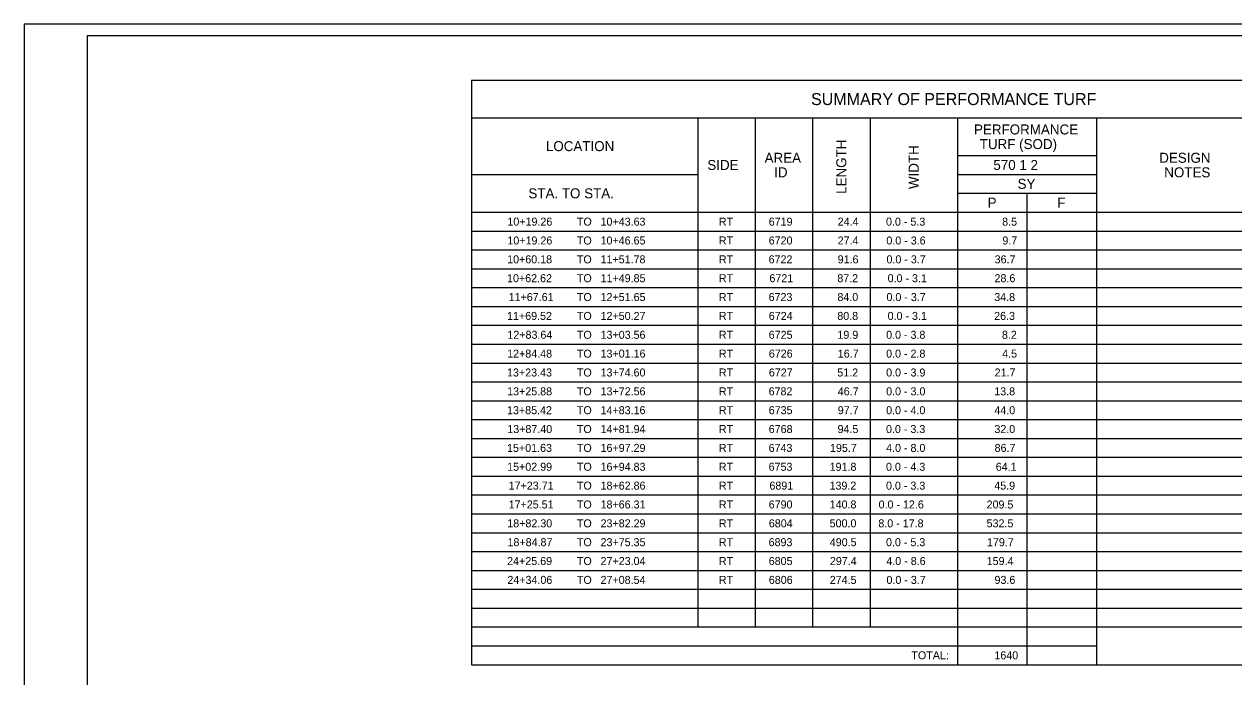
# Model space of a CAD drawing. Extents: x -831.4 to -734.9, y -2212.7 to -2202.1.
# Drawn here: x -751.39 to -740.81, y -2207.85 to -2202.14 of the extents above; entities that cross this region are included whole.
import ezdxf

# ---------------------------------------------------------------- set-up
doc = ezdxf.new("R2010")
doc.units = 0
for name, color, linetype in [('PlotBorder_dp', 7, 'Continuous'), ('SheetBorder_dp', 7, 'Continuous'), ('SumBoxBorder_dp', 7, 'Continuous'), ('SumBoxLines_dp', 7, 'Continuous'), ('SumBoxLinesMin_dp', 7, 'Continuous'), ('TextLabel', 7, 'Continuous')]:
    doc.layers.add(name, color=color, linetype=linetype)

msp = doc.modelspace()

# ---------------------------------------------------------------- linework, layer by layer
at = {"layer": 'PlotBorder_dp'}
msp.add_lwpolyline([(-751.391, -2212.74), (-734.891, -2212.74), (-734.891, -2202.14), (-751.391, -2202.14)], close=True, dxfattribs=at)
at = {"layer": 'SheetBorder_dp'}
for q in [(-750.841, -2212.64), (-735.441, -2202.24)]:
    msp.add_line((-750.841, -2202.24), q, dxfattribs=at)
at = {"layer": 'SumBoxBorder_dp'}
for p, q in [((-747.479, -2202.63), (-738.802, -2202.63)), ((-747.479, -2202.63), (-747.479, -2207.745)), ((-747.479, -2207.745), (-738.802, -2207.745))]:
    msp.add_line(p, q, dxfattribs=at)
at = {"layer": 'SumBoxLines_dp'}
for p, q in [((-747.479, -2202.96), (-738.802, -2202.96)), ((-747.479, -2202.96), (-738.802, -2202.96)), ((-745.499, -2202.96), (-745.499, -2207.415)), ((-745.499, -2202.96), (-745.499, -2207.415)), ((-744.997, -2202.96), (-744.997, -2207.415)), ((-744.997, -2202.96), (-744.997, -2207.415)), ((-744.494, -2202.96), (-744.494, -2207.415)), ((-744.494, -2202.96), (-744.494, -2207.415)), ((-743.992, -2202.96), (-743.992, -2207.415)), ((-743.992, -2202.96), (-743.992, -2207.415)), ((-743.227, -2202.96), (-743.227, -2207.745)), ((-743.227, -2202.96), (-743.227, -2207.745)), ((-742.012, -2202.96), (-742.012, -2207.745)), ((-742.012, -2202.96), (-742.012, -2207.745)), ((-743.227, -2203.29), (-742.012, -2203.29)), ((-743.227, -2203.29), (-742.012, -2203.29)), ((-747.479, -2203.455), (-745.499, -2203.455)), ((-747.479, -2203.455), (-745.499, -2203.455)), ((-743.227, -2203.455), (-742.012, -2203.455)), ((-743.227, -2203.455), (-742.012, -2203.455)), ((-743.227, -2203.62), (-742.012, -2203.62)), ((-743.227, -2203.62), (-742.012, -2203.62)), ((-747.479, -2203.785), (-738.802, -2203.785)), ((-747.479, -2203.785), (-738.802, -2203.785)), ((-747.479, -2207.415), (-743.227, -2207.415)), ((-742.012, -2207.415), (-738.802, -2207.415))]:
    msp.add_line(p, q, dxfattribs=at)
at = {"layer": 'SumBoxLinesMin_dp'}
for p, q in [((-742.619, -2203.62), (-742.619, -2207.745)), ((-742.619, -2203.62), (-742.619, -2207.745)), ((-747.479, -2203.95), (-738.802, -2203.95)), ((-747.479, -2203.95), (-738.802, -2203.95)), ((-747.479, -2204.115), (-738.802, -2204.115)), ((-747.479, -2204.115), (-738.802, -2204.115)), ((-747.479, -2204.28), (-738.802, -2204.28)), ((-747.479, -2204.28), (-738.802, -2204.28)), ((-747.479, -2204.445), (-738.802, -2204.445)), ((-747.479, -2204.445), (-738.802, -2204.445)), ((-747.479, -2204.61), (-738.802, -2204.61)), ((-747.479, -2204.61), (-738.802, -2204.61)), ((-747.479, -2204.775), (-738.802, -2204.775)), ((-747.479, -2204.775), (-738.802, -2204.775)), ((-747.479, -2204.94), (-738.802, -2204.94)), ((-747.479, -2204.94), (-738.802, -2204.94)), ((-747.479, -2205.105), (-738.802, -2205.105)), ((-747.479, -2205.105), (-738.802, -2205.105)), ((-747.479, -2205.27), (-738.802, -2205.27)), ((-747.479, -2205.27), (-738.802, -2205.27)), ((-747.479, -2205.435), (-738.802, -2205.435)), ((-747.479, -2205.435), (-738.802, -2205.435)), ((-747.479, -2205.6), (-738.802, -2205.6)), ((-747.479, -2205.6), (-738.802, -2205.6)), ((-747.479, -2205.765), (-738.802, -2205.765)), ((-747.479, -2205.765), (-738.802, -2205.765)), ((-747.479, -2205.93), (-738.802, -2205.93)), ((-747.479, -2205.93), (-738.802, -2205.93)), ((-747.479, -2206.095), (-738.802, -2206.095)), ((-747.479, -2206.095), (-738.802, -2206.095)), ((-747.479, -2206.26), (-738.802, -2206.26)), ((-747.479, -2206.26), (-738.802, -2206.26)), ((-747.479, -2206.425), (-738.802, -2206.425)), ((-747.479, -2206.425), (-738.802, -2206.425)), ((-747.479, -2206.59), (-738.802, -2206.59)), ((-747.479, -2206.59), (-738.802, -2206.59)), ((-747.479, -2206.755), (-738.802, -2206.755)), ((-747.479, -2206.755), (-738.802, -2206.755)), ((-747.479, -2206.92), (-738.802, -2206.92)), ((-747.479, -2206.92), (-738.802, -2206.92)), ((-747.479, -2207.085), (-738.802, -2207.085)), ((-747.479, -2207.085), (-738.802, -2207.085)), ((-747.479, -2207.25), (-738.802, -2207.25)), ((-747.479, -2207.25), (-738.802, -2207.25)), ((-743.227, -2207.415), (-742.012, -2207.415)), ((-743.227, -2207.415), (-742.012, -2207.415)), ((-747.479, -2207.58), (-742.012, -2207.58)), ((-747.479, -2207.58), (-742.012, -2207.58))]:
    msp.add_line(p, q, dxfattribs=at)

# ---------------------------------------------------------------- texts
at = {"layer": 'TextLabel'}
for s, height, p in [('SUMMARY OF PERFORMANCE TURF', 0.105, (-744.508, -2202.848)), ('PERFORMANCE', 0.0875, (-743.082, -2203.105)), ('TURF (SOD)', 0.0875, (-743.032, -2203.233)), ('LOCATION', 0.0875, (-746.827, -2203.251)), ('AREA', 0.0875, (-744.914, -2203.353)), ('DESIGN', 0.0875, (-741.462, -2203.353)), ('SIDE', 0.0875, (-745.415, -2203.416)), ('570 1 2', 0.0875, (-742.913, -2203.416)), ('ID', 0.0875, (-744.83, -2203.48)), ('NOTES', 0.0875, (-741.418, -2203.48)), ('STA. TO STA.', 0.0875, (-746.98, -2203.664)), ('SY', 0.0875, (-742.701, -2203.581)), ('P', 0.0875, (-742.963, -2203.746)), ('F', 0.0875, (-742.354, -2203.746)), ('10+19.26', 0.07, (-747.164, -2203.903)), ('TO', 0.07, (-746.556, -2203.903)), ('10+43.63', 0.07, (-746.349, -2203.903)), ('RT', 0.07, (-745.314, -2203.903)), ('6719', 0.07, (-744.878, -2203.903)), ('24.4', 0.07, (-744.275, -2203.903)), ('0.0 - 5.3', 0.07, (-743.852, -2203.903)), ('8.5', 0.07, (-742.836, -2203.903)), ('10+19.26', 0.07, (-747.164, -2204.068)), ('TO', 0.07, (-746.556, -2204.068)), ('10+46.65', 0.07, (-746.349, -2204.068)), ('RT', 0.07, (-745.314, -2204.068)), ('6720', 0.07, (-744.878, -2204.068)), ('27.4', 0.07, (-744.275, -2204.068)), ('0.0 - 3.6', 0.07, (-743.849, -2204.068)), ('9.7', 0.07, (-742.834, -2204.068)), ('10+60.18', 0.07, (-747.166, -2204.233)), ('TO', 0.07, (-746.556, -2204.233)), ('11+51.78', 0.07, (-746.349, -2204.233)), ('RT', 0.07, (-745.314, -2204.233)), ('6722', 0.07, (-744.879, -2204.233)), ('91.6', 0.07, (-744.275, -2204.233)), ('0.0 - 3.7', 0.07, (-743.848, -2204.233)), ('36.7', 0.07, (-742.902, -2204.233)), ('10+62.62', 0.07, (-747.167, -2204.398)), ('TO', 0.07, (-746.556, -2204.398)), ('11+49.85', 0.07, (-746.349, -2204.398)), ('RT', 0.07, (-745.314, -2204.398)), ('6721', 0.07, (-744.872, -2204.398)), ('87.2', 0.07, (-744.278, -2204.398)), ('0.0 - 3.1', 0.07, (-743.838, -2204.398)), ('28.6', 0.07, (-742.903, -2204.398)), ('11+67.61', 0.07, (-747.153, -2204.563)), ('TO', 0.07, (-746.556, -2204.563)), ('12+51.65', 0.07, (-746.349, -2204.563)), ('RT', 0.07, (-745.314, -2204.563)), ('6723', 0.07, (-744.879, -2204.563)), ('84.0', 0.07, (-744.277, -2204.563)), ('0.0 - 3.7', 0.07, (-743.848, -2204.563)), ('34.8', 0.07, (-742.905, -2204.563)), ('11+69.52', 0.07, (-747.167, -2204.728)), ('TO', 0.07, (-746.556, -2204.728)), ('12+50.27', 0.07, (-746.349, -2204.728)), ('RT', 0.07, (-745.314, -2204.728)), ('6724', 0.07, (-744.877, -2204.728)), ('80.8', 0.07, (-744.278, -2204.728)), ('0.0 - 3.1', 0.07, (-743.838, -2204.728)), ('26.3', 0.07, (-742.906, -2204.728)), ('12+83.64', 0.07, (-747.164, -2204.893)), ('TO', 0.07, (-746.556, -2204.893)), ('13+03.56', 0.07, (-746.349, -2204.893)), ('RT', 0.07, (-745.314, -2204.893)), ('6725', 0.07, (-744.878, -2204.893)), ('19.9', 0.07, (-744.277, -2204.893)), ('0.0 - 3.8', 0.07, (-743.851, -2204.893)), ('8.2', 0.07, (-742.838, -2204.893)), ('12+84.48', 0.07, (-747.166, -2205.058)), ('TO', 0.07, (-746.556, -2205.058)), ('13+01.16', 0.07, (-746.349, -2205.058)), ('RT', 0.07, (-745.314, -2205.058)), ('6726', 0.07, (-744.877, -2205.058)), ('16.7', 0.07, (-744.274, -2205.058)), ('0.0 - 2.8', 0.07, (-743.851, -2205.058)), ('4.5', 0.07, (-742.836, -2205.058)), ('13+23.43', 0.07, (-747.167, -2205.223)), ('TO', 0.07, (-746.556, -2205.223)), ('13+74.60', 0.07, (-746.349, -2205.223)), ('RT', 0.07, (-745.314, -2205.223)), ('6727', 0.07, (-744.877, -2205.223)), ('51.2', 0.07, (-744.278, -2205.223)), ('0.0 - 3.9', 0.07, (-743.851, -2205.223)), ('21.7', 0.07, (-742.902, -2205.223)), ('13+25.88', 0.07, (-747.166, -2205.388)), ('TO', 0.07, (-746.556, -2205.388)), ('13+72.56', 0.07, (-746.349, -2205.388)), ('RT', 0.07, (-745.314, -2205.388)), ('6782', 0.07, (-744.879, -2205.388)), ('46.7', 0.07, (-744.274, -2205.388)), ('0.0 - 3.0', 0.07, (-743.851, -2205.388)), ('13.8', 0.07, (-742.905, -2205.388)), ('13+85.42', 0.07, (-747.167, -2205.553)), ('TO', 0.07, (-746.556, -2205.553)), ('14+83.16', 0.07, (-746.349, -2205.553)), ('RT', 0.07, (-745.314, -2205.553)), ('6735', 0.07, (-744.878, -2205.553)), ('97.7', 0.07, (-744.274, -2205.553)), ('0.0 - 4.0', 0.07, (-743.851, -2205.553)), ('44.0', 0.07, (-742.904, -2205.553)), ('13+87.40', 0.07, (-747.165, -2205.718)), ('TO', 0.07, (-746.556, -2205.718)), ('14+81.94', 0.07, (-746.349, -2205.718)), ('RT', 0.07, (-745.314, -2205.718)), ('6768', 0.07, (-744.878, -2205.718)), ('94.5', 0.07, (-744.276, -2205.718)), ('0.0 - 3.3', 0.07, (-743.852, -2205.718)), ('32.0', 0.07, (-742.904, -2205.718)), ('15+01.63', 0.07, (-747.167, -2205.883)), ('TO', 0.07, (-746.556, -2205.883)), ('16+97.29', 0.07, (-746.349, -2205.883)), ('RT', 0.07, (-745.314, -2205.883)), ('6743', 0.07, (-744.879, -2205.883)), ('195.7', 0.07, (-744.342, -2205.883)), ('4.0 - 8.0', 0.07, (-743.851, -2205.883)), ('86.7', 0.07, (-742.902, -2205.883)), ('15+02.99', 0.07, (-747.166, -2206.048)), ('TO', 0.07, (-746.556, -2206.048)), ('16+94.83', 0.07, (-746.349, -2206.048)), ('RT', 0.07, (-745.314, -2206.048)), ('6753', 0.07, (-744.879, -2206.048)), ('191.8', 0.07, (-744.345, -2206.048)), ('0.0 - 4.3', 0.07, (-743.852, -2206.048)), ('64.1', 0.07, (-742.892, -2206.048)), ('17+23.71', 0.07, (-747.153, -2206.213)), ('TO', 0.07, (-746.556, -2206.213)), ('18+62.86', 0.07, (-746.349, -2206.213)), ('RT', 0.07, (-745.314, -2206.213)), ('6891', 0.07, (-744.872, -2206.213)), ('139.2', 0.07, (-744.346, -2206.213)), ('0.0 - 3.3', 0.07, (-743.852, -2206.213)), ('45.9', 0.07, (-742.905, -2206.213)), ('17+25.51', 0.07, (-747.153, -2206.378)), ('TO', 0.07, (-746.556, -2206.378)), ('18+66.31', 0.07, (-746.349, -2206.378)), ('RT', 0.07, (-745.314, -2206.378)), ('6790', 0.07, (-744.878, -2206.378)), ('140.8', 0.07, (-744.345, -2206.378)), ('0.0 - 12.6', 0.07, (-743.917, -2206.378)), ('209.5', 0.07, (-742.972, -2206.378)), ('18+82.30', 0.07, (-747.165, -2206.543)), ('TO', 0.07, (-746.556, -2206.543)), ('23+82.29', 0.07, (-746.349, -2206.543)), ('RT', 0.07, (-745.314, -2206.543)), ('6804', 0.07, (-744.877, -2206.543)), ('500.0', 0.07, (-744.345, -2206.543)), ('8.0 - 17.8', 0.07, (-743.919, -2206.543)), ('532.5', 0.07, (-742.972, -2206.543)), ('18+84.87', 0.07, (-747.163, -2206.708)), ('TO', 0.07, (-746.556, -2206.708)), ('23+75.35', 0.07, (-746.349, -2206.708)), ('RT', 0.07, (-745.314, -2206.708)), ('6893', 0.07, (-744.879, -2206.708)), ('490.5', 0.07, (-744.344, -2206.708)), ('0.0 - 5.3', 0.07, (-743.852, -2206.708)), ('179.7', 0.07, (-742.969, -2206.708)), ('24+25.69', 0.07, (-747.166, -2206.873)), ('TO', 0.07, (-746.556, -2206.873)), ('27+23.04', 0.07, (-746.349, -2206.873)), ('RT', 0.07, (-745.314, -2206.873)), ('6805', 0.07, (-744.878, -2206.873)), ('297.4', 0.07, (-744.343, -2206.873)), ('4.0 - 8.6', 0.07, (-743.849, -2206.873)), ('159.4', 0.07, (-742.971, -2206.873)), ('24+34.06', 0.07, (-747.164, -2207.038)), ('TO', 0.07, (-746.556, -2207.038)), ('27+08.54', 0.07, (-746.349, -2207.038)), ('RT', 0.07, (-745.314, -2207.038)), ('6806', 0.07, (-744.877, -2207.038)), ('274.5', 0.07, (-744.344, -2207.038)), ('0.0 - 3.7', 0.07, (-743.848, -2207.038)), ('93.6', 0.07, (-742.903, -2207.038)), ('TOTAL:', 0.07, (-743.63, -2207.698)), ('1640', 0.07, (-742.904, -2207.698))]:
    msp.add_text(s, height=height, dxfattribs=at).set_placement(p)
for s, p in [('LENGTH', (-744.199, -2203.625)), ('WIDTH', (-743.566, -2203.583))]:
    msp.add_text(s, height=0.0875, rotation=90, dxfattribs=at).set_placement(p)

doc.saveas('drawing.dxf')
